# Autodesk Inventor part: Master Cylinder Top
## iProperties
Shininess: 41.0
Angle Display Precision: 2
Document Length Units: 11269
Document Angle Units: 11279
Document Time Units: 11290
Document Mass Units: 11283
Document Length Units Precision: 3
Document Angle Units Precision: 2
Compacted: True
Created: 2001-08
Part Number: Master Cylinder Top
Document SubType Name: Modeling
Designer: Martin Budgell
Density: 0.0
Volumn: 0.0
Area: 0.0
PropertySet Name: Model Information
Control State: 0
Master: False
Checked Out: False
Author: Martin Budgell
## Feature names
1. Extrusion1
2. Chamfer1
